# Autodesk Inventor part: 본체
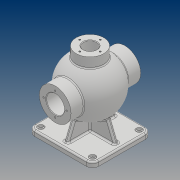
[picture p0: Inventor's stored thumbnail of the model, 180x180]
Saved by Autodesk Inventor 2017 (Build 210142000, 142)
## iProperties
Part Number: 본체
Material: 일반
Document SubType Name: Modeling
Designer: 13
Density: 1 g/cm^3
Appearance: 기본값
Mass: 557.04 g
Surface Area: 1153.86 cm^2
Volume: 557.04 cm^3
Author: 13
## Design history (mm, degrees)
sketch "스케치1"
  geometry: L1 (53, 0)-(-53, 0); A1 r 53 centre (0, 0) between (53, 0) and (-53, 0); 1 further point
  constraints: 2 end point, 2 horizontal alignment, 2 point on circle, 1 centre point, 1 coincident, 1 horizontal
  dimensions: "d1" = 53 radius of A1
revolve "회전1" sketch "스케치1" stored, may be unused: angle "d2" = 90 deg
sketch "스케치2"
  geometry: L1 (43, 0)-(-43, 0); L2 (0, 0)-(-100, 0); A1 r 43 centre (0, 0) between (43, 0) and (-43, 0); 1 further point
  constraints: 4 end point, 2 horizontal alignment, 2 point on circle, 1 centre point, 1 coincident, 1 horizontal, 1 midpoint, 1 point on line
  dimensions: "d3" = 43 radius of A1; "d4" = 100 distance of L2.start L2.end
revolve "회전2" sketch "스케치2" stored, may be unused: angle "d5" = 90 deg
node "작업 평면2"
sketch "스케치3"
  geometry: C1 r 31 at (0, 0); 1 further point
  constraints: 1 centre point, 1 coincident
  dimensions: "d8" = 62 diameter of C1
extrude "돌출1" join sketch "스케치3" stored distance "d9" = 10; taper "d10" = 0 deg
sketch "스케치4"
  geometry: C1 r 17.5 at (0, 0); 1 further point
  constraints: 1 centre point, 1 coincident
  dimensions: "d11" = 35 diameter of C1
extrude "돌출2" cut sketch "스케치4" stored distance "d12" = 10; taper "d13" = 0 deg
node "작업 평면3"
sketch "스케치5"
  geometry: C1 r 27 at (0, 0); 1 further point
  constraints: 1 centre point, 1 coincident
  dimensions: "d15" = 54 diameter of C1
extrude "돌출3" join sketch "스케치5" stored distance "d16" = 10; taper "d17" = 0 deg
sketch "스케치6"
  geometry: C1 r 13 at (0, 0); 1 further point
  constraints: 1 centre point, 1 coincident
  dimensions: "d18" = 26 diameter of C1
extrude "돌출4" cut sketch "스케치6" distance "d19" = 40; taper "d20" = 0 deg
node "작업 평면4"
sketch "스케치7"
  geometry: C1 r 18.5 at (0, 0); 1 further point
  constraints: 1 centre point, 1 coincident
  dimensions: "d22" = 37 diameter of C1
extrude "돌출5" cut sketch "스케치7" distance "d23" = 1.75; taper "d24" = 0 deg
node "작업 평면5"
sketch "스케치8"
  geometry: L1 (-62.5, 57.5)-(62.5, 57.5); L2 (62.5, 57.5)-(62.5, -57.5); L3 (62.5, -57.5)-(-62.5, -57.5); L4 (-62.5, -57.5)-(-62.5, 57.5); L5 (-62.5, 57.5)-(62.5, -57.5); L6 (62.5, 57.5)-(-62.5, -57.5); 1 further point
  constraints: 12 end point, 2 midpoint, 2 parallel, 1 horizontal, 1 perpendicular
  dimensions: "d26" = 115 distance of L1.end L2.end; "d27" = 125 distance of L1.start L1.end
extrude "돌출6" join sketch "스케치8" distance "d28" = 10; taper "d29" = 0 deg
sketch "스케치9"
  geometry: L1 (-4, 4)-(4, 4); L2 (4, 4)-(4, -4); L3 (4, -4)-(-4, -4); L4 (-4, -4)-(-4, 4); L5 (-4, 4)-(4, -4); L6 (4, 4)-(-4, -4); 1 further point
  constraints: 12 end point, 2 midpoint, 2 parallel, 1 horizontal, 1 perpendicular
  dimensions: "d30" = 8 distance of L2.end L3.end; "d31" = 8 distance of L1.end L2.end
extrude "돌출7" join sketch "스케치9" stored distance "d32" = 10; taper "d33" = 0 deg
sketch "스케치10"
  geometry: L1 (52.5, -75)-(39.167, -42); L2 (62.5, -85)-(62.5, -75) reference; L3 (-62.5, -75)-(62.5, -75) reference; 1 further point
  constraints: 2 end point, 1 point on line
  dimensions: "d34" = 10 distance from line of L1.start L2; "d36" = 22 deg angle of L2 L1; "d37" = 33 vertical distance of L1.start L1.end
feature "리브1" sketch "스케치10" dims "d38" = 1, "d39" = 8, "d40" = 0, "d41" = 0, "d42" = 1, "d43" = 1
sketch "스케치11"
  geometry: L1 (-52.5, -75)-(-42.399, -50); L2 (-62.5, -85)-(-62.5, -75) reference; L3 (62.5, -75)-(-62.5, -75) reference; 1 further point
  constraints: 2 end point, 1 point on line
  dimensions: "d44" = 10 distance from line of L2 L1.start; "d45" = 22 deg angle of L2 L1; "d46" = 25 vertical distance of L1.start L1.end
feature "리브2" sketch "스케치11" dims "d47" = 1, "d48" = 8, "d49" = 0, "d50" = 0, "d51" = 1, "d52" = 1
sketch "스케치12"
  geometry: L1 (-47.5, -75)-(-37.399, -50); L2 (-57.5, -85)-(-57.5, -75) reference; L3 (57.5, -75)-(-57.5, -75) reference; 1 further point
  constraints: 2 end point, 1 point on line
  dimensions: "d53" = 10 distance from line of L1.start L2; "d54" = 22 deg angle of L2 L1; "d55" = 25 vertical distance of L1.start L1.end
feature "리브3" sketch "스케치12" dims "d56" = 1, "d57" = 8, "d58" = 0, "d59" = 0, "d60" = 1, "d61" = 1
sketch "스케치13"
  geometry: L1 (47.5, -75)-(37.399, -50); L2 (57.5, -85)-(57.5, -75) reference; L3 (57.5, -75)-(-57.5, -75) reference; 1 further point
  constraints: 2 end point, 1 point on line
  dimensions: "d62" = 10 distance from line of L2 L1.start; "d63" = 22 deg angle of L2 L1; "d64" = 25 vertical distance of L1.start L1.end
feature "리브4" sketch "스케치13" dims "d65" = 1, "d66" = 8, "d67" = 0, "d68" = 0, "d69" = 1, "d70" = 1
fillet "모깎기1" dims "d71" = 12
sketch "스케치15"
  geometry: 2 further points
  constraints: 1 vertical alignment
  dimensions: "d75" = 22.5 distance of point (0, 0) point (0, 22.5)
hole "구멍1" sketch "스케치15" at (0, 22.5) diameter "d76" = 3.242; stored, may be unused: countersink angle "d80" = 90 deg, drill point angle "d82" = 118 deg; dims "d77" = 12, "d78" = 4, "d79" = 2, "d81" = 15
sketch "스케치16"
  geometry: 2 further points
  constraints: 1 vertical alignment
  dimensions: "d86" = 24 distance of point (0, -24) point (0, 0)
hole "구멍2" sketch "스케치16" at (0, -24) diameter "d87" = 3.242; stored, may be unused: countersink angle "d91" = 90 deg, drill point angle "d93" = 118 deg; dims "d88" = 16, "d89" = 4, "d90" = 2, "d92" = 19
sketch "스케치17"
  geometry: L1 (-4, -4)-(-4, -33.66) reference; 2 further points
  constraints: 1 vertical alignment
  dimensions: "d97" = 20 distance of point (0, -20) point (0, 0)
hole "구멍3" sketch "스케치17" at (0, -20) diameter "d98" = 3.242; stored, may be unused: countersink angle "d102" = 90 deg, drill point angle "d104" = 118 deg; dims "d99" = 9, "d100" = 4, "d101" = 2, "d103" = 11
chamfer "모따기1" distance "d108" = 1; stored, may be unused: second distance "d109" = 2, angle "d110" = 45 deg
sketch "스케치18"
  geometry: A1 r 12 centre (-50.5, 45.5) between (-50.5, 57.5) and (-62.5, 45.5) reference; A2 r 12 centre (50.5, 45.5) between (62.5, 45.5) and (50.5, 57.5) reference; A3 r 12 centre (50.5, -45.5) between (50.5, -57.5) and (62.5, -45.5) reference; A4 r 12 centre (-50.5, -45.5) between (-62.5, -45.5) and (-50.5, -57.5) reference; 5 further points
  constraints: 4 coincident
hole "구멍4" sketch "스케치18" at (-50.5, 45.5), (50.5, 45.5), (50.5, -45.5), (-50.5, -45.5) diameter "d111" = 8; stored, may be unused: countersink angle "d115" = 90 deg, drill point angle "d117" = 118 deg; dims "d112" = 9, "d113" = 12, "d114" = 3, "d116" = 11
fillet "모깎기2" dims "d118" = 3
fillet "모깎기3" dims "d119" = 3
node "작업 평면6"
sketch "스케치19"
  geometry: L1 (-27, 65)-(-27, 47.286) reference; L2 (-27, 65)-(27, 65) reference; 2 further points
  constraints: 1 other
  dimensions: "d121" = 27 distance from line of point (0, 55) L1; "d122" = 10 distance from line of point (0, 55) L2
feature "엠보싱1" sketch "스케치19" dims "d1" = 53, "d123" = 0.5, "d124" = 0
node "솔리드1"
mirror "미러1"
pattern_circular "원형 패턴1" dims angle "d84" = 360 deg
pattern_circular "원형 패턴2" dims angle "d95" = 360 deg
pattern_circular "원형 패턴3" dims angle "d106" = 360 deg
other parameters: "d7" = -68, "d14" = 65, "d21" = -16, "d25" = -85, "d120" = -65.75
